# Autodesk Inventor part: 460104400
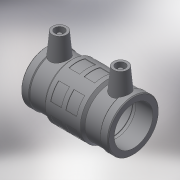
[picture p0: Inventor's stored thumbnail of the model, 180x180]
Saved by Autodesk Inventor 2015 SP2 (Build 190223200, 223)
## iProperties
Created: 2017-06
Part Number: 460104400
Material: Generic
Description: PLASSON LIGHTFIT COUPLER 400
Document SubType Name: Modeling
Designer: KIM
Mass: 89.5427 g
Surface Area: 304.58 cm^2
Volume: 89.5427 cm^3
Density: 1 g/cm^3
Appearance: Default
Author: KIM
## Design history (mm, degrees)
derived "460104.ipt"
feature "Solid1::460104.ipt"
tag "TaggingFeature1"
body "Solid1"
other parameters: "d13" = 296, "d14" = 17.6296, "d15" = 146, "d16" = 146, "d17" = 396, "d19" = 3.52592, "d20" = 168 deg, "d22" = 445.56, "d23" = 474, "d24" = 432.1932, "d25" = 135 deg, "d26" = 118.4, "d27" = 135 deg, "d29" = 227, "d35" = 15, "d39" = 5 deg, "d44" = 4, "d46" = 14, "d47" = 0, "d52" = 464.52, "d53" = 14.8, "d54" = 14.8, "d55" = 14.8, "d56" = 35 deg, "d58" = 360 deg, "d60" = 29.2, "d61" = 135 deg, "d62" = 133.2, "d63" = 3, "d64" = 0, "L_" = 296, "L_1" = 146, "D_" = 474, "A_" = 227, "d_2" = 12
